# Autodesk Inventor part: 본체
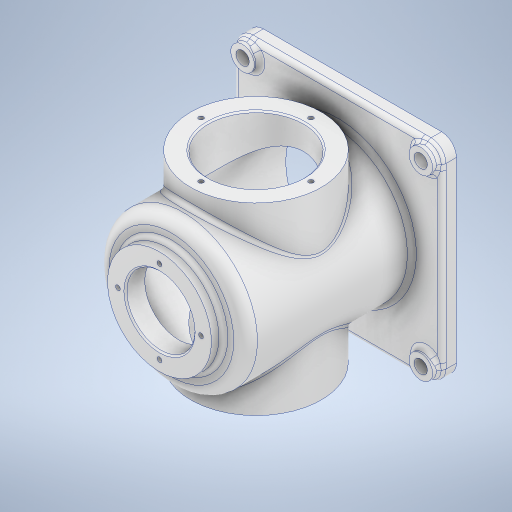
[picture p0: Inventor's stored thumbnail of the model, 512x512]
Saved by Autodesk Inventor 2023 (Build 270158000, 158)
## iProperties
Created: 2025-05
Part Number: 본체
Material: 알루미늄 6061
Document SubType Name: Modeling
Designer: user
Density: 2.7 g/cm^3
Appearance: 알루미늄 - 평지
Mass: 1130.9 g
Surface Area: 1201.4 cm^2
Volume: 418.852 cm^3
Author: user
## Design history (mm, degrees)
sketch "스케치3"
  geometry: C1 r 50 at (0, 0); 1 further point
  constraints: 1 centre point, 1 coincident
  dimensions: "d0" = 100 diameter of C1
extrude "돌출1" new body sketch "스케치3" distance "d1" = 122; taper "d2" = 0 deg
sketch "스케치9"
  geometry: L1 (-70, -70)-(70, -70); L2 (70, -70)-(70, 70); L3 (70, 70)-(-70, 70); L4 (-70, 70)-(-70, -70); L5 (-70, -70)-(70, 70); L6 (70, -70)-(-70, 70); 1 further point
  constraints: 12 end point, 2 midpoint, 2 parallel, 1 horizontal, 1 perpendicular
  dimensions: "d12" = 140 distance of L3.end L2.end; "d13" = 140 distance of L2.end L1.end
extrude "돌출4" join sketch "스케치9" distance "d14" = 10; taper "d15" = 0 deg
sketch "스케치12"
  geometry: L1 (-72.836, 65)-(75.341, 65); L2 (-70, 0)-(70, 0) reference; L3 (0, -24.4)-(0, 146.4) reference; C1 r 44 at (0, 65); 1 further point
  constraints: 2 end point, 2 point on line, 1 centre point, 1 horizontal
  dimensions: "d19" = 65 distance between parallel lines of L2 L1; "d20" = 88 diameter of C1
extrude "돌출6" join sketch "스케치12" stored distance "d21" = 124; taper "d22" = 0 deg
sketch "스케치10"
  geometry: C1 r 45 at (0, 0); 1 further point
  constraints: 1 centre point, 1 coincident
  dimensions: "d16" = 90 diameter of C1
extrude "돌출5" cut sketch "스케치10" distance "d17" = 117; taper "d18" = 0 deg
sketch "스케치13"
  geometry: L1 (0, 89.4)-(0, -81.4) reference; L2 (64.744, 0)-(-80.929, 0); L3 (-70, 65)-(70, 65) reference; C1 r 32 at (0, 0); 1 further point
  constraints: 2 end point, 2 point on line, 1 centre point, 1 horizontal
  dimensions: "d23" = 64 diameter of C1; "d24" = 65 distance between parallel lines of L3 L2
extrude "돌출7" cut sketch "스케치13" extent not by distance; stored distance "d25" = 0; taper "d26" = 0 deg
sketch "스케치15"
  geometry: C1 r 35 at (0, 0); 1 further point
  constraints: 1 centre point, 1 coincident
  dimensions: "d27" = 70 diameter of C1
extrude "돌출8" join sketch "스케치15" distance "d28" = 8; taper "d29" = 0 deg
sketch "스케치16"
  geometry: C1 r 23 at (0, 0); 1 further point
  constraints: 1 centre point, 1 coincident
  dimensions: "d30" = 46 diameter of C1
extrude "돌출9" cut sketch "스케치16" extent not by distance; stored distance "d31" = 0; taper "d32" = 0 deg
sketch "스케치17"
  geometry: L1 (-98, 0)-(98, 0) reference; L2 (0, -98)-(0, 98) reference; 2 further points
  constraints: 1 point on line
  dimensions: "d34" = 56 diameter of point (-28, 0) L2
hole "구멍1" sketch "스케치17" at (-28, 0) diameter "d35" = 3.242; stored, may be unused: countersink angle "d39" = 90 deg, drill point angle "d41" = 118 deg; dims "d36" = 6, "d37" = 4, "d38" = 2, "d40" = 10
sketch "스케치18"
  geometry: L1 (0, -91)-(0, 91) reference; L2 (-79.6, 0)-(91.263, 0); L3 (70, -65)-(-70, -65) reference; 2 further points
  constraints: 2 end point, 1 horizontal, 1 point on line
  dimensions: "d45" = 65 distance between parallel lines of L3 L2; "d46" = 74 diameter of point (0, 37) L2
hole "구멍2" sketch "스케치18" at (0, 37) diameter "d47" = 3.242; stored, may be unused: countersink angle "d51" = 90 deg, drill point angle "d53" = 118 deg; dims "d48" = 6, "d49" = 4, "d50" = 2, "d52" = 10
fillet "모깎기1" dims "d57" = 10
sketch "스케치19"
  geometry: C1 r 8 at (60, 60); C2 r 8 at (60, -60); C3 r 8 at (-60, 60); C4 r 8 at (-60, -60); A1 r 10 centre (60, 60) between (70, 60) and (60, 70) reference; A2 r 10 centre (60, -60) between (60, -70) and (70, -60) reference; A3 r 10 centre (-60, 60) between (-60, 70) and (-70, 60) reference; A4 r 10 centre (-60, -60) between (-70, -60) and (-60, -70) reference; 1 further point
  constraints: 4 centre point, 4 coincident
  dimensions: "d58" = 16 diameter of C1; "d59" = 16 diameter of C2; "d60" = 16 diameter of C3; "d61" = 16 diameter of C4
extrude "돌출10" join sketch "스케치19" distance "d62" = 4; taper "d63" = 0 deg
sketch "스케치20"
  geometry: 1 further point
sketch "스케치21"
  geometry: C1 r 8 at (0, -120) reference; C2 r 4.5 at (0, -120); C3 r 4.5 at (-120, -120); C4 r 8 at (-120, 0) reference; C5 r 4.5 at (-120, 0); C6 r 4.5 at (0, 0); A1 r 10 centre (-120, -120) between (-130, -120) and (-120, -130) reference; A2 r 10 centre (0, 0) between (10, 0) and (0, 10) reference; 1 further point
  constraints: 4 centre point, 4 coincident
  dimensions: "d65" = 9 diameter of C2; "d66" = 9 diameter of C3; "d67" = 9 diameter of C5; "d68" = 9 diameter of C6
extrude "돌출11" cut sketch "스케치21" extent not by distance; stored distance "d69" = 4; taper "d70" = 0 deg
node "작업 평면3"
sketch "스케치25" dims "d1" = 122, "d2" = 0
  geometry: L1 (0, -26)-(0, 156) reference; L2 (60, 0)-(-60, 0) reference; 2 further points
  constraints: 1 point on line, 1 other
  dimensions: "d77" = 80 distance from line of L2 point (0, 80)
feature "엠보싱2" sketch "스케치25" dims "d1" = 122, "d2" = 0, "d78" = 0.5, "d79" = 0
fillet "모깎기2" dims "d80" = 3
chamfer "모따기1" distance "d81" = 1; stored, may be unused: second distance "d82" = 2, angle "d83" = 45 deg
fillet "모깎기3" dims "d84" = 8
node "솔리드1"
pattern_circular "원형 패턴1" dims angle "d43" = 360 deg
pattern_circular "원형 패턴2" dims angle "d55" = 360 deg
mirror "미러1"
feature "A9D066F2-1C7D-4E18-AEED-F7BC21143FA4" dims "d35" = 3.242, "d36" = 6, "d37" = 4, "d38" = 2, "d39" = 90 deg, "d40" = 10, "d41" = 118 deg
other parameters: "d76" = -187.75
